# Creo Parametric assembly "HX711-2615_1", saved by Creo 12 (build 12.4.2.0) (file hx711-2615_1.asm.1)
Units: Custom; MM, KILOGRAM, SECS

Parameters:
  PTC_WM_ITERATION = "0"
  PTC_WM_VERSION = "-.0"
  PTC_WM_LIFECYCLE_STATE = "In Work"
  PTC_WM_LIFECYCLE = "MO_CADDocument"
  PTC_WM_CREATED_BY = "Maximilian Roepper (Z0017RMS: MO)"
  PTC_WM_CREATED_ON = "18-Sep-26 11:36:42 AM"
  PTC_WM_MODIFIED_BY = "Maximilian Roepper (Z0017RMS: MO)"
  PTC_WM_MODIFIED_ON = "18-Sep-26 11:36:46 AM"
  PDMLINKNUMBER = "PDM000071455249"
  PTC_WM_NUMBER = "PDM000071455249"

Other parameters: WEIGHT, WEIGHT_FACTOR, WEIGHT_ADD, MC_ERRORS, SUPPLIER

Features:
  1. coordinate system
  2. imported feature
  3. component "MODELL_ASM_1"

Other named items: DRW_VIEW_ORG, ROUGH-GROB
